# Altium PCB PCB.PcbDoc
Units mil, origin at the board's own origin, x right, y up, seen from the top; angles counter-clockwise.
Board outline 3937.01 x 3937.01 mil, 2 copper layers (Top Layer, Bottom Layer); 30 components, 19 nets, 76 pads, 0 vias.
Unrouted connection lines stored in the file: 14.
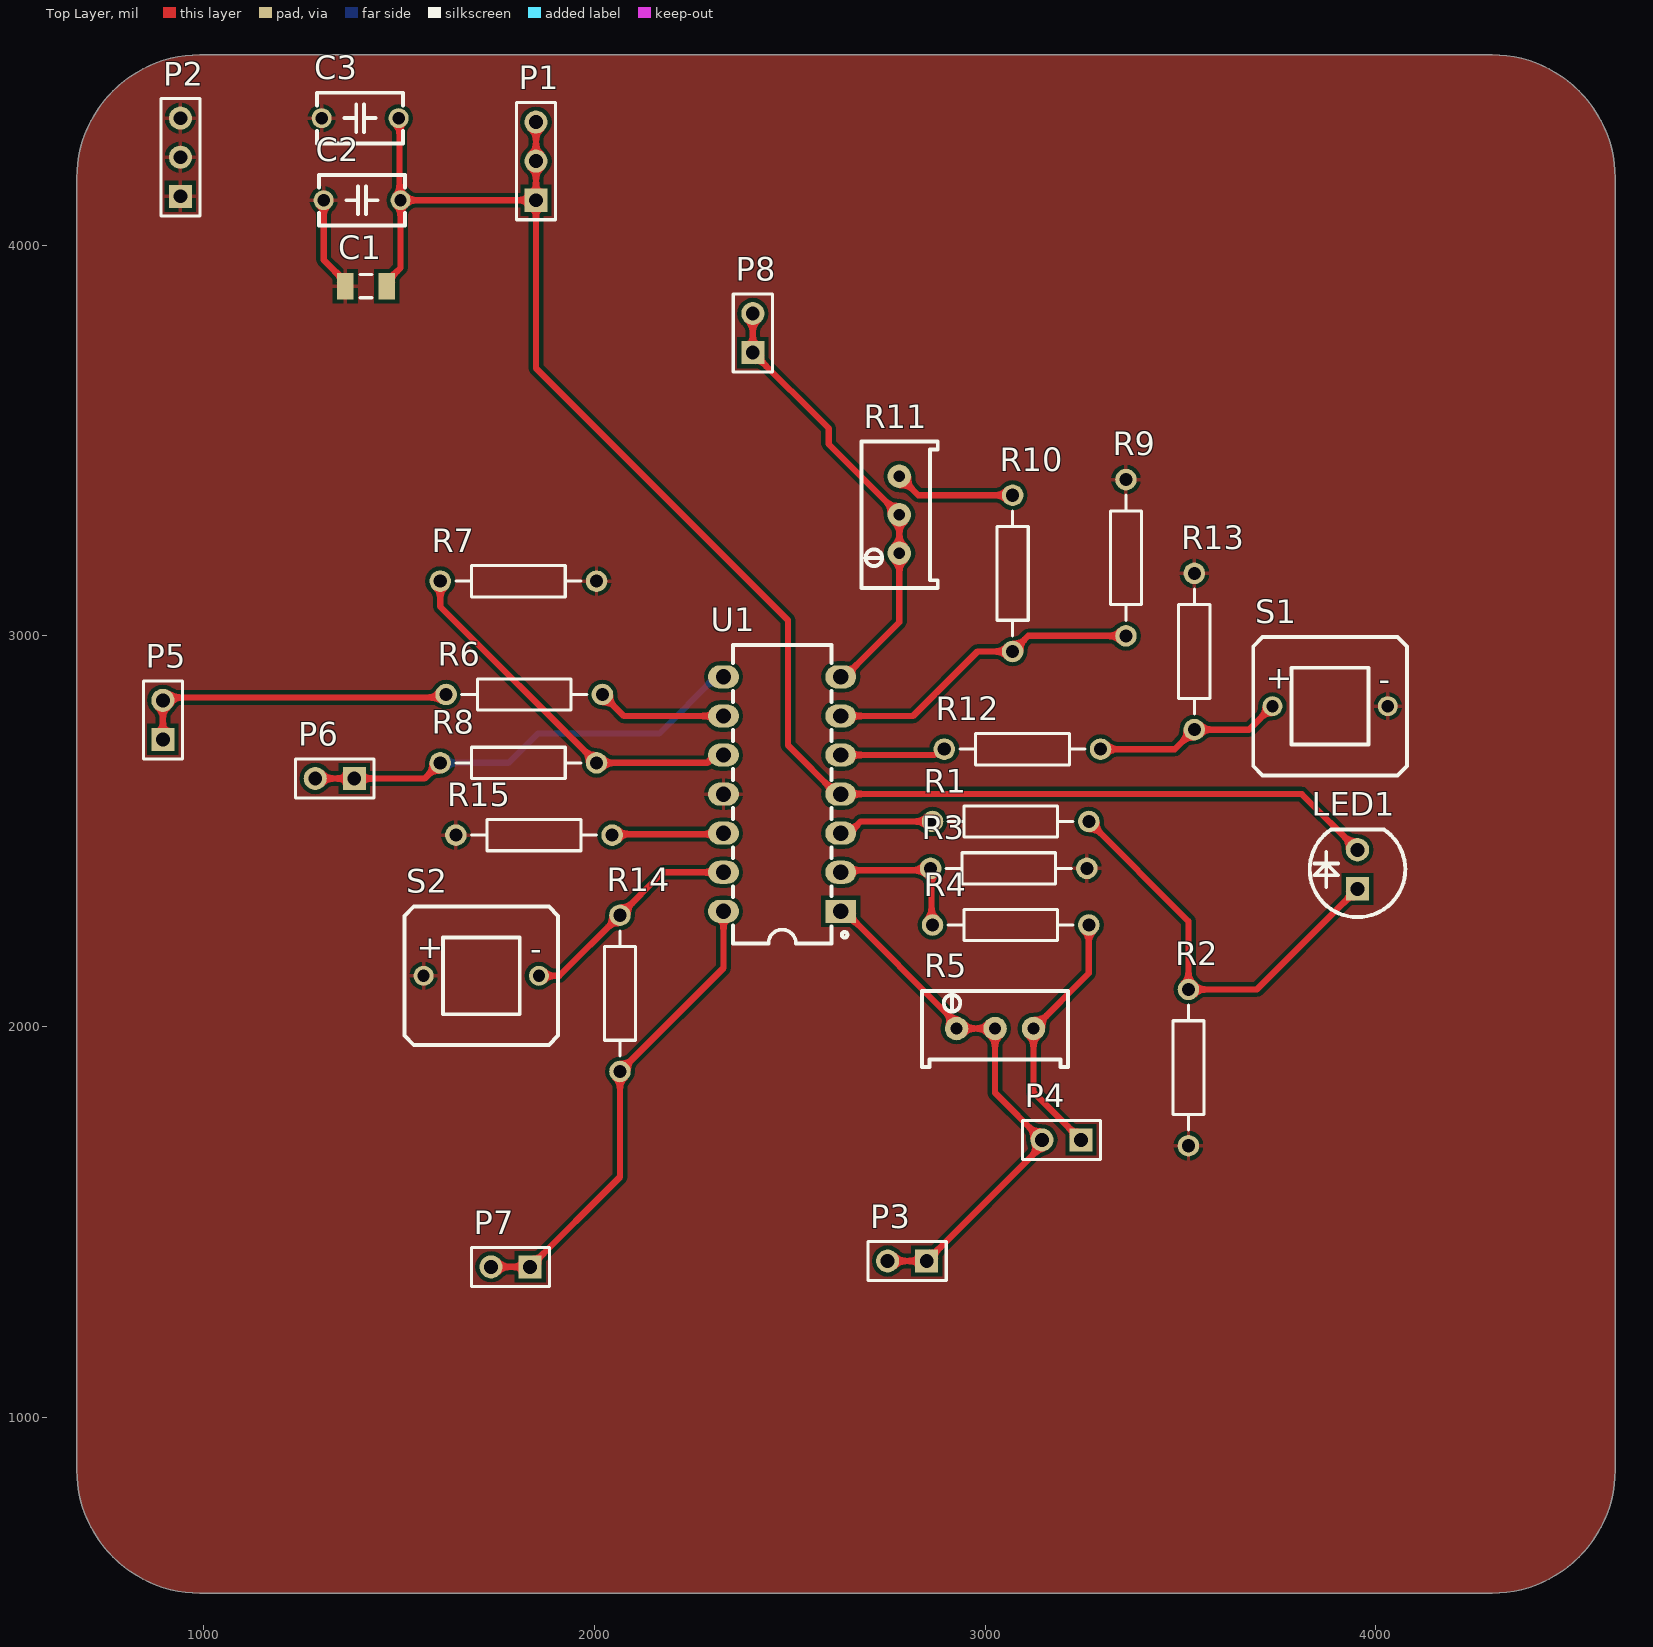
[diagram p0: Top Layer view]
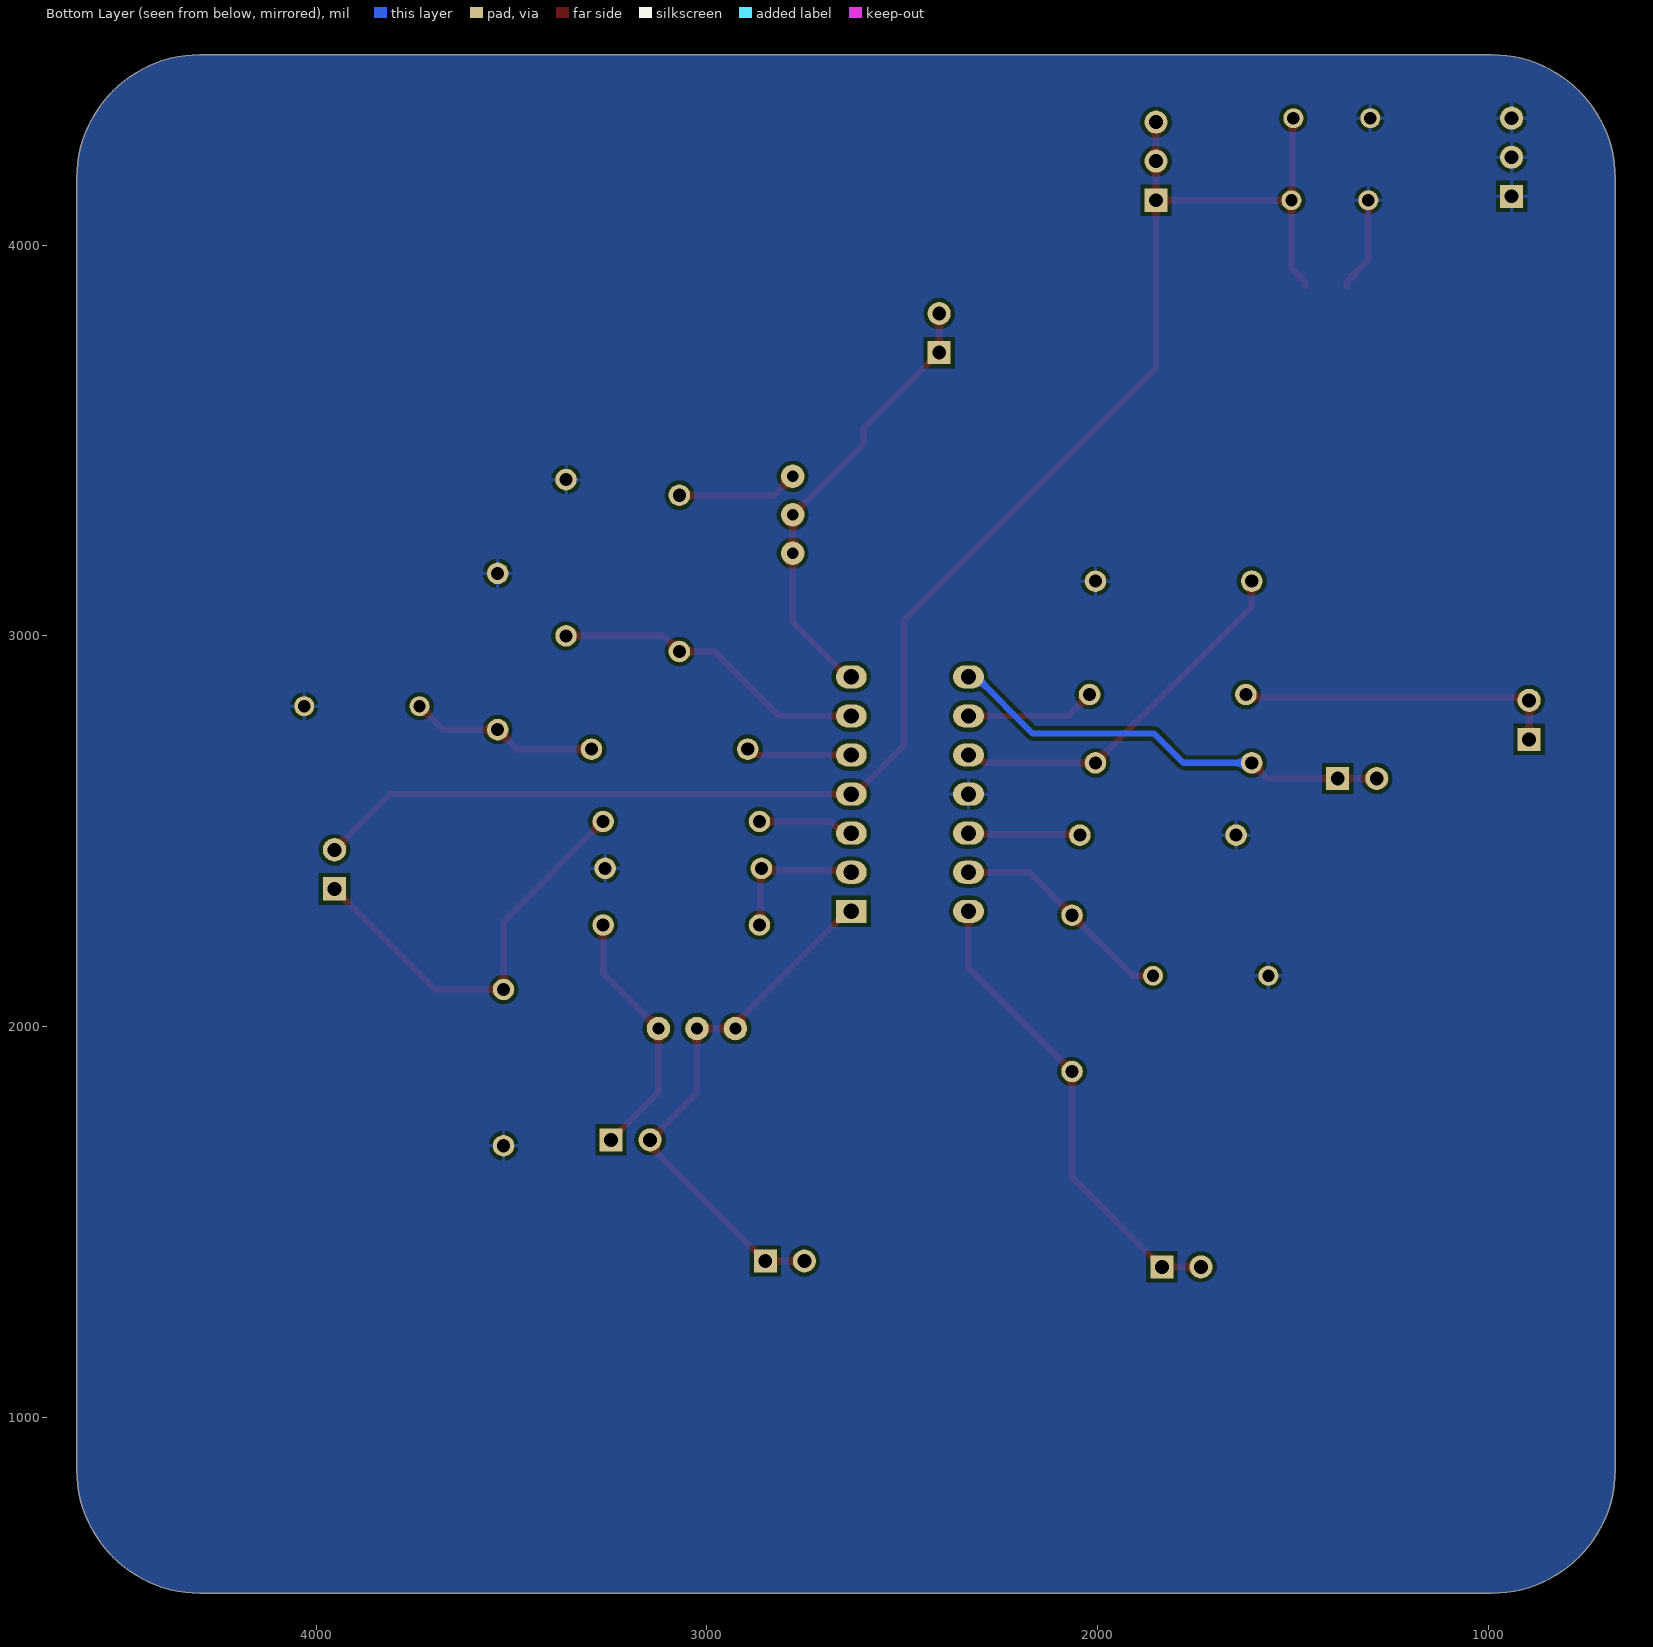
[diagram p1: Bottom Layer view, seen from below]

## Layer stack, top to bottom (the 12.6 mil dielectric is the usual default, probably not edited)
Top Solder: solder mask 0.4, Solder Resist, Dk 3.5
Top Layer: signal copper 1.4
Dielectric 1: dielectric 12.6, FR-4, Dk 4.8
Bottom Layer: signal copper 1.4
Bottom Solder: solder mask 0.4, Solder Resist, Dk 3.5

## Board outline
675,864.96 ccw(c989.96,864.96) 989.96,550 4297.05,550 ccw(c4297.05,864.96) 4612.01,864.96 4612.01,4172.05 ccw(c4297.05,4172.05) 4297.05,4487.01 989.96,4487.01 ccw(c989.96,4172.05) 675,4172.05

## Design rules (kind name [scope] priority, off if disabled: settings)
Clearance [All] p1: gap=10 ignorepadtopadclearanceinfootprint=FALSE except(0: Arc-Hole Track-Hole SMDPad-Hole THPad-Hole Via-Hole Fill-Hole Poly-Hole Region-Hole Text-Hole)
PolygonConnect [All] p1: connectstyle=Relief reliefconductorwidth=10 reliefentries=4 polygonreliefangle="90 Angle" airgapwidth=10
RoutingVias [All] p1: holewidth=28 width=50 viastyle="Through Hole" minholewidth=28 minwidth=50 maxholewidth=28 maxwidth=50
SolderMaskExpansion [All] p1: expansion=4
Width [All] p1: maxlimit=32 minlimit=8 preferedwidth=16 minimp=50.000000 maximp=50.000000 favimp=50.000000
30 further rules are at their usual default settings.

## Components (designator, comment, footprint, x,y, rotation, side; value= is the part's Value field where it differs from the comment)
C1 "Cap Semi" C1206 1415,3895 r0 top value=10uF
C2 "Cap Semi" CAP-TH_L5.5-W3.0-P5.00-D0.6 1405,4115 r0 top value=0.1uF
C3 "Cap Semi" CAP-TH_L5.5-W3.0-P5.00-D0.6 1400,4325 r0 top value=0.1uF
LED1 "SFH203PFA" LED-TH_BD5.9-P2.54-FD 3950,2405 r90 top
P1 "5V" HDR1X3 1850,4115 r90 top
P2 "GND" HDR1X3 940,4125 r90 top
P3 "O1T" HDR1X2 2850,1400 r180 top
P4 "TM" HDR1X2 3245,1710 r180 top
P5 "CMIN" HDR1X2 895,2735 r90 top
P6 "CM" HDR1X2 1385,2635 r180 top
P7 "CM" HDR1X2 1835,1385 r180 top
P8 "CM" HDR1X2 2405,3725 r90 top
R1 "Res2" AXIAL-0.4 3065,2525 r0 top value=1K
R2 "Res2" AXIAL-0.4 3520,1895 r90 top value=10K
R3 "Res2" AXIAL-0.4 3060,2405 r180 top value=1K
R4 "Res2" AXIAL-0.4 3065,2260 r0 top value=10K
R5 "RPot" RES-ADJ-TH_3P-L10.0-W10.0-P2.50-L 3025,1995 r0 top value=50K
R6 "Res2" AXIAL-0.4 1820,2850 r0 top value=5.1K
R7 "Res2" AXIAL-0.4 1805,3140 r180 top value=10K
R8 "Res2" AXIAL-0.4 1805,2675 r180 top value=10K
R9 "Res2" AXIAL-0.4 3360,3200 r270 top value=10K
R10 "Res2" AXIAL-0.4 3070,3160 r90 top value=10K
R11 "RPot" RES-ADJ-TH_3P-L10.0-W10.0-P2.50-L 2780,3310 r90 top value=50K
R12 "Res2" AXIAL-0.4 3095,2710 r180 top value=10K
R13 "Res2" AXIAL-0.4 3535,2960 r270 top value=10K
R14 "Res2" AXIAL-0.4 2065,2085 r270 top value=3K
R15 "Res2" AXIAL-0.4 1845,2490 r0 top value=3K
S1 "2DU6" 2DU6PERSONAL 3882.64,2820 r0 top
S2 "2DU6" 2DU6PERSONAL 1710,2130 r0 top
U1 "LM324N" DIP-14_L19.4-W6.4-P2.54-LS7.6-BL 2389.37,1802.4 r90 top

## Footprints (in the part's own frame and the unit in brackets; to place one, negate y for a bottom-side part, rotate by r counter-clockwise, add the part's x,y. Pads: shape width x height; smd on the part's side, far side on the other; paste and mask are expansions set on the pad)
2DU6PERSONAL [mm]
  round 1.3 hole 0.8: 1(-3.75,0) 2(3.75,0)
  silkscreen extent -5,-4.5 5,4.5
AXIAL-0.4 [mm] "Axial Device, Thru-Hole; 2 Leads; 0.4 in Pin Spacing"
  round 1.4 hole 0.85: 1(-5.08,0) 2(5.08,0)
  silkscreen extent -4.06,-1.02 4.06,1.02
C1206 [mm] "Chip Capacitor, Body 3.2x1.6mm, IPC High Density"
  rect 1.1x1.7 smd: 1(-1.35,0) 2(1.35,0)
  silkscreen extent -0.4,-0.75 0.4,0.75, body extent -1.7,-0.9 1.7,0.9, height 1.3
CAP-TH_L5.5-W3.0-P5.00-D0.6 [mm]
  round 1.3 hole 0.8: 1(-2.5,0) 2(2.5,0)
  silkscreen extent -2.79,-1.65 2.79,1.65
DIP-14_L19.4-W6.4-P2.54-LS7.6-BL [mm]
  rect 1.5x2 hole 1: 1(12.512,-6.112)
  oval 1.5x2 hole 1: 2(15.052,-6.112) 3(17.592,-6.112) 4(20.132,-6.112) 5(22.672,-6.112) 6(25.212,-6.112) 7(27.752,-6.112) 8(27.752,1.508) 9(25.212,1.508) 10(22.672,1.508) 11(20.132,1.508) 12(17.592,1.508) 13(15.052,1.508) 14(12.512,1.508)
  silkscreen extent 10.43,-6.55 29.83,0.9
HDR1X2 [mm] "Connector; Header; 2 Position"
  rect 1.5x1.5 hole 0.9: 1(0,0)
  round 1.5 hole 0.9: 2(2.54,0)
  silkscreen extent -1.27,-1.27 3.81,1.27
HDR1X3 [mm] "Connector; Header; 3 Position"
  rect 1.5x1.5 hole 0.9: 1(0,0)
  round 1.5 hole 0.9: 2(2.54,0) 3(5.08,0)
  silkscreen extent -1.27,-1.27 6.35,1.27
LED-TH_BD5.9-P2.54-FD [mil]
  rect 60x60 hole 36: 1(-52.64,-2.67)
  round 60 hole 36: 2(47.36,-2.67)
  silkscreen extent -125,-125 100,120
RES-ADJ-TH_3P-L10.0-W10.0-P2.50-L [mil]
  round 60 hole 30: 1(-98.42,0) 2(98.43,0) 3(0,0)
  silkscreen extent -187,-98 187,96

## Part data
C1 C2 C3: "Capacitor (Semiconductor SIM Model)"
LED1: BOM_JLCPCB Part Class="Extended Part", BOM_Manufacturer="OSRAM Opto Semicon"
P1 P2: library part "Header 3", "Header, 3-Pin"
P3 P4 P5 P6 P7 P8: library part "Header 2", "Header, 2-Pin"
R1 R2 R3 R4 R6 R7 R8 R9 R10 R12 R13 R14 R15: "Resistor"
R5 R11: "Potentiometer"
U1: BOM_JLCPCB Part Class="Extended Part", BOM_Manufacturer=HGSEMI

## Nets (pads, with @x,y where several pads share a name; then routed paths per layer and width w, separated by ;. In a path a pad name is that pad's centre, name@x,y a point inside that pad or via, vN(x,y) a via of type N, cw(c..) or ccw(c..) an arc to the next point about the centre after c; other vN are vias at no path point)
GND: C1.1 C2.1 C3.1 P2.1 P2.2 P2.3 R2.1 R3.1 R7.1 R9.1 R13.1 R15.1 S1.2 S2.1 U1.11 | length 242.9
  Top Layer w16: C2.1 1306.57,3962.09 1361.85,3906.81 C1.1
NetLED1_1: LED1.1 R1.2 R2.2 | length 1074.9
  Top Layer w16: R1.2 3520,2270 R2.2 3695.31,2095 LED1.1
NetP3_1: P3.1 P3.2 P4.2 R5.1 R5.3 U1.1 | length 1393.9
  Top Layer w16: U1.1 2639.84,2295 2918.16,2016.69 2918.16,2003.42 R5.1 R5.3 3025,1830 P4.2 3136.76,1701.76 3136.76,1686.76 P3.1 P3.2
NetP4_1: P4.1 R4.2 R5.2 | length 659
  Top Layer w16: P4.1 3123.43,1831.58 R5.2 3265,2136.58 R4.2
NetP5_1: P5.1 P5.2 R6.1 | length 831.2
  Top Layer w16: P5.1 P5.2 902.52,2842.52 1612.52,2842.52 R6.1
NetP6_1: P6.1 P6.2 R8.2 U1.8 | length 1152.7
  Top Layer w16: P6.2 P6.1 1565,2635 R8.2
  Bottom Layer w16: R8.2 1780,2675 1855,2750 2165,2750 2310,2895 U1.8
NetP7_1: P7.1 P7.2 R14.2 U1.14 | length 1215
  Top Layer w16: P7.2 P7.1 2065,1615 R14.2 2330,2150 U1.14
NetP8_1: P8.1 P8.2 R11.1 R11.3 U1.7 | length 1153.2
  Top Layer w16: P8.2 P8.1 2599.05,3530.95 2599.05,3490.95 R11.3 R11.1 2780,3035.16 2639.84,2895 U1.7
NetR1_1: R1.1 U1.3 | length 247.4
  Top Layer w16: U1.3 2651.49,2495 2681.49,2525 R1.1
NetR3_2: R3.2 R4.1 U1.2 | length 381.2
  Top Layer w16: U1.2 2635,2400 2855,2400 R3.2 2862.5,2402.5 2862.5,2262.5 R4.1
NetR6_2: R6.2 U1.9 | length 332.8
  Top Layer w16: R6.2 2075,2795 U1.9
NetR7_2: R7.2 R8.1 U1.10 | length 964
  Top Layer w16: R7.2 1605,3075 R8.1 2288.51,2675 2308.51,2695 U1.10
NetR9_2: R9.2 R10.1 U1.6 | length 814.9
  Top Layer w16: U1.6 2815,2795 2980,2960 R10.1 3110,3000 R9.2
NetR10_2: R10.2 R11.2 | length 310.1
  Top Layer w16: R11.2 2828.43,3360 R10.2
NetR12_1: R12.1 R13.2 S1.1 | length 485.6
  Top Layer w16: R12.1 3485,2710 R13.2 3675,2760 S1.1
NetR12_2: R12.2 U1.5 | length 271.2
  Top Layer w16: U1.5 2869.41,2695 2884.41,2710 R12.2
NetR14_1: R14.1 S2.2 U1.13 | length 582.1
  Top Layer w16: S2.2 1910,2130 R14.1 2175,2395 U1.13
NetR15_2: R15.2 U1.12 | length 287.1
  Top Layer w16: R15.2 2047.5,2492.5 2327.5,2492.5 U1.12
VCC_5V: C1.2 C2.2 C3.2 LED1.2 P1.1 P1.2 P1.3 U1.4 | length 4223.9
  Top Layer w16: C1.2 1468.15,3906.81 1503.42,3942.08 C2.2 ; C3.2 1500.92,4322.5 1500.92,4117.5 C2.2 ; P1.3 P1.2 P1.1 ; LED1.2 3810.02,2595 U1.4 2620.16,2595 2495,2720.16 2495,3040 1850,3685 P1.1 ; C2.2 P1.1

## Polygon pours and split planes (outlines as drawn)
GND on Top Layer "Top Layer-No Net" (solid, remove dead copper, pour order 17): 675,864.96 ccw(c989.96,864.96) 989.96,550 4297.05,550 ccw(c4297.05,864.96) 4612.01,864.96 4612.01,4172.05 ccw(c4297.05,4172.05) 4297.05,4487.01 989.96,4487.01 ccw(c989.96,4172.05) 675,4172.05
GND on Bottom Layer "Top Layer-No Net1" (solid, remove dead copper, pour order 18): 675,864.96 ccw(c989.96,864.96) 989.96,550 4297.05,550 ccw(c4297.05,864.96) 4612.01,864.96 4612.01,4172.05 ccw(c4297.05,4172.05) 4297.05,4487.01 989.96,4487.01 ccw(c989.96,4172.05) 675,4172.05

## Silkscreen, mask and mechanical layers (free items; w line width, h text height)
Mechanical 1:
  the board outline again, w10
